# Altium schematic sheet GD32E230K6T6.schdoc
size 127 x 101 mm
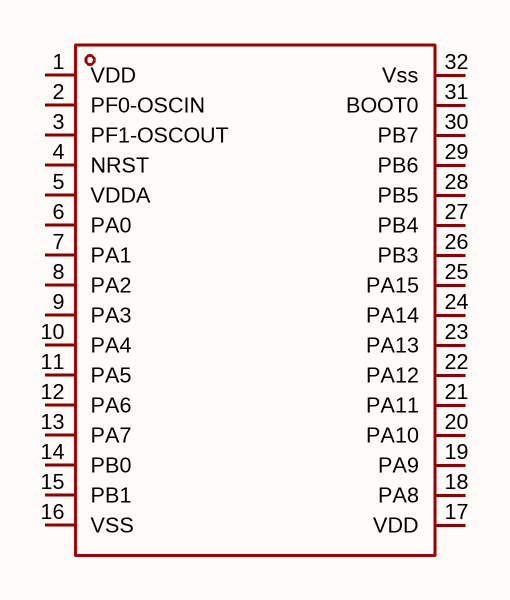
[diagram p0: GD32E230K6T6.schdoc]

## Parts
U?  gd32e230k6t6  [LQFP-32_L7.0-W7.0-P0.80-LS9.0-BL]  (value not drawn)

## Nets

Not connected (* = marked no-connect by the designer): U? 1(VDD) 2(PF0-OSCIN) 3(PF1-OSCOUT) 4(NRST) 5(VDDA) 6(PA0) 7(PA1) 8(PA2) 9(PA3) 10(PA4) 11(PA5) 12(PA6) 13(PA7) 14(PB0) 15(PB1) 16(VSS) 17(VDD) 18(PA8) 19(PA9) 20(PA10) 21(PA11) 22(PA12) 23(PA13) 24(PA14) 25(PA15) 26(PB3) 27(PB4) 28(PB5) 29(PB6) 30(PB7) 31(BOOT0) 32(Vss)

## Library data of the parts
U? = gd32e230k6t6: CPU内核:ARM Cortex-M系列;CPU最大主频:72MHz;; Manufacturer: GigaDevice(兆易创新); AddInBom: yes; ModelId: 9b055eb510f041fea358114a6302af34; ModelName: LQFP-32_L7.0-W7.0-H1.4-LS9.0-P0.80; ModelTransform: 354.331,354.331,0,0,0,0,0,0,0; CPU Maximum Speed: 72MHz; Program Storage Size: 32KB; Program Memory Type: FLASH; Number of I/O: 25; ADC (Bit): 12bit; Voltage - Supply: 1.8V~3.6V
